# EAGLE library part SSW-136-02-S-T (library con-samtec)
THROUGH-HOLE .025" SQ POST SOCKET Source: Samtec SSW.pdf
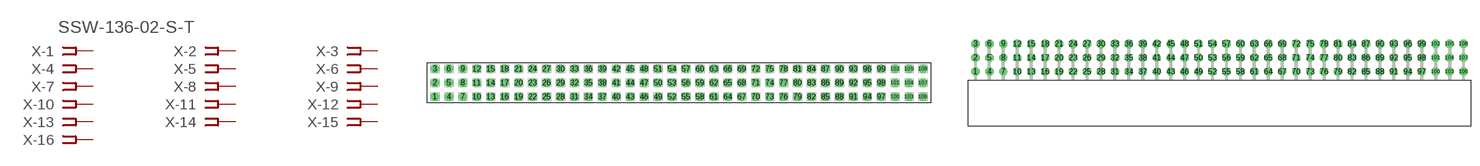
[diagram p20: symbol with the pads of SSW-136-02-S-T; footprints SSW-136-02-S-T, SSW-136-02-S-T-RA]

Designator prefix X; gates -1=FPINV -2=FPIN -3=FPIN -4=FPIN -5=FPIN -6=FPIN -7=FPIN -8=FPIN -9=FPIN -10=FPIN -11=FPIN -12=FPIN -13=FPIN -14=FPIN -15=FPIN -16=FPIN -17=FPIN -18=FPIN -19=FPIN -20=FPIN -21=FPIN -22=FPIN -23=FPIN -24=FPIN -25=FPIN -26=FPIN -27=FPIN -28=FPIN -29=FPIN -30=FPIN -31=FPIN -32=FPIN -33=FPIN -34=FPIN -35=FPIN -36=FPIN -37=FPIN -38=FPIN -39=FPIN -40=FPIN -41=FPIN -42=FPIN -43=FPIN -44=FPIN -45=FPIN -46=FPIN -47=FPIN -48=FPIN -49=FPIN -50=FPIN -51=FPIN -52=FPIN -53=FPIN -54=FPIN -55=FPIN -56=FPIN -57=FPIN -58=FPIN -59=FPIN -60=FPIN -61=FPIN -62=FPIN -63=FPIN -64=FPIN -65=FPIN -66=FPIN -67=FPIN -68=FPIN -69=FPIN -70=FPIN -71=FPIN -72=FPIN -73=FPIN -74=FPIN -75=FPIN -76=FPIN -77=FPIN -78=FPIN -79=FPIN -80=FPIN -81=FPIN -82=FPIN -83=FPIN -84=FPIN -85=FPIN -86=FPIN -87=FPIN -88=FPIN -89=FPIN -90=FPIN -91=FPIN -92=FPIN -93=FPIN -94=FPIN -95=FPIN -96=FPIN -97=FPIN -98=FPIN -99=FPIN -100=FPIN -101=FPIN -102=FPIN -103=FPIN -104=FPIN -105=FPIN -106=FPIN -107=FPIN -108=FPIN

## SSW-136-02-S-T (MPN: SSW-136-02-S-T; OC_FARNELL: unknown; OC_NEWARK: 83P0980)  [SSW-136-02-S-T]
1  -1:1  pas
2  -2:1  pas
3  -3:1  pas
4  -4:1  pas
5  -5:1  pas
6  -6:1  pas
7  -7:1  pas
8  -8:1  pas
9  -9:1  pas
10  -10:1  pas
11  -11:1  pas
12  -12:1  pas
13  -13:1  pas
14  -14:1  pas
15  -15:1  pas
16  -16:1  pas
17  -17:1  pas
18  -18:1  pas
19  -19:1  pas
20  -20:1  pas
21  -21:1  pas
22  -22:1  pas
23  -23:1  pas
24  -24:1  pas
25  -25:1  pas
26  -26:1  pas
27  -27:1  pas
28  -28:1  pas
29  -29:1  pas
30  -30:1  pas
31  -31:1  pas
32  -32:1  pas
33  -33:1  pas
34  -34:1  pas
35  -35:1  pas
36  -36:1  pas
37  -37:1  pas
38  -38:1  pas
39  -39:1  pas
40  -40:1  pas
41  -41:1  pas
42  -42:1  pas
43  -43:1  pas
44  -44:1  pas
45  -45:1  pas
46  -46:1  pas
47  -47:1  pas
48  -48:1  pas
49  -49:1  pas
50  -50:1  pas
51  -51:1  pas
52  -52:1  pas
53  -53:1  pas
54  -54:1  pas
55  -55:1  pas
56  -56:1  pas
57  -57:1  pas
58  -58:1  pas
59  -59:1  pas
60  -60:1  pas
61  -61:1  pas
62  -62:1  pas
63  -63:1  pas
64  -64:1  pas
65  -65:1  pas
66  -66:1  pas
67  -67:1  pas
68  -68:1  pas
69  -69:1  pas
70  -70:1  pas
71  -71:1  pas
72  -72:1  pas
73  -73:1  pas
74  -74:1  pas
75  -75:1  pas
76  -76:1  pas
77  -77:1  pas
78  -78:1  pas
79  -79:1  pas
80  -80:1  pas
81  -81:1  pas
82  -82:1  pas
83  -83:1  pas
84  -84:1  pas
85  -85:1  pas
86  -86:1  pas
87  -87:1  pas
88  -88:1  pas
89  -89:1  pas
90  -90:1  pas
91  -91:1  pas
92  -92:1  pas
93  -93:1  pas
94  -94:1  pas
95  -95:1  pas
96  -96:1  pas
97  -97:1  pas
98  -98:1  pas
99  -99:1  pas
100  -100:1  pas
101  -101:1  pas
102  -102:1  pas
103  -103:1  pas
104  -104:1  pas
105  -105:1  pas
106  -106:1  pas
107  -107:1  pas
108  -108:1  pas

## SSW-136-02-S-TRA (MPN: SSW-136-02-S-T-RA; OC_FARNELL: unknown; OC_NEWARK: 83P0981)  [SSW-136-02-S-T-RA]
Pads as for SSW-136-02-S-T

## Footprint SSW-136-02-S-T (pad centres in mm)
THROUGH-HOLE .025" SQ POST SOCKET Source: Samtec SSW.pdf
drill 1 pad 1.5 octagon: 1 -44.45,-2.54; 2 -44.45,0; 3 -44.45,2.54; 4 -41.91,-2.54; 5 -41.91,0; 6 -41.91,2.54; 7 -39.37,-2.54; 8 -39.37,0; 9 -39.37,2.54; 10 -36.83,-2.54; 11 -36.83,0; 12 -36.83,2.54; 13 -34.29,-2.54; 14 -34.29,0; 15 -34.29,2.54; 16 -31.75,-2.54; 17 -31.75,0; 18 -31.75,2.54; 19 -29.21,-2.54; 20 -29.21,0; 21 -29.21,2.54; 22 -26.67,-2.54; 23 -26.67,0; 24 -26.67,2.54; 25 -24.13,-2.54; 26 -24.13,0; 27 -24.13,2.54; 28 -21.59,-2.54; 29 -21.59,0; 30 -21.59,2.54; 31 -19.05,-2.54; 32 -19.05,0; 33 -19.05,2.54; 34 -16.51,-2.54; 35 -16.51,0; 36 -16.51,2.54; 37 -13.97,-2.54; 38 -13.97,0; 39 -13.97,2.54; 40 -11.43,-2.54; 41 -11.43,0; 42 -11.43,2.54; 43 -8.89,-2.54; 44 -8.89,0; 45 -8.89,2.54; 46 -6.35,-2.54; 47 -6.35,0; 48 -6.35,2.54; 49 -3.81,-2.54; 50 -3.81,0; 51 -3.81,2.54; 52 -1.27,-2.54; 53 -1.27,0; 54 -1.27,2.54; 55 1.27,-2.54; 56 1.27,0; 57 1.27,2.54; 58 3.81,-2.54; 59 3.81,0; 60 3.81,2.54; 61 6.35,-2.54; 62 6.35,0; 63 6.35,2.54; 64 8.89,-2.54; 65 8.89,0; 66 8.89,2.54; 67 11.43,-2.54; 68 11.43,0; 69 11.43,2.54; 70 13.97,-2.54; 71 13.97,0; 72 13.97,2.54; 73 16.51,-2.54; 74 16.51,0; 75 16.51,2.54; 76 19.05,-2.54; 77 19.05,0; 78 19.05,2.54; 79 21.59,-2.54; 80 21.59,0; 81 21.59,2.54; 82 24.13,-2.54; 83 24.13,0; 84 24.13,2.54; 85 26.67,-2.54; 86 26.67,0; 87 26.67,2.54; 88 29.21,-2.54; 89 29.21,0; 90 29.21,2.54; 91 31.75,-2.54; 92 31.75,0; 93 31.75,2.54; 94 34.29,-2.54; 95 34.29,0; 96 34.29,2.54; 97 36.83,-2.54; 98 36.83,0; 99 36.83,2.54; 100 39.37,-2.54; 101 39.37,0; 102 39.37,2.54; 103 41.91,-2.54; 104 41.91,0; 105 41.91,2.54; 106 44.45,-2.54; 107 44.45,0; 108 44.45,2.54

## Footprint SSW-136-02-S-T-RA (pad centres in mm)
THROUGH-HOLE .025" SQ POST SOCKET Source: Samtec SSW.pdf
drill 1 pad 1.5 octagon: 1 -44.45,1.524; 2 -44.45,4.064; 3 -44.45,6.604; 4 -41.91,1.524; 5 -41.91,4.064; 6 -41.91,6.604; 7 -39.37,1.524; 8 -39.37,4.064; 9 -39.37,6.604; 10 -36.83,1.524; 11 -36.83,4.064; 12 -36.83,6.604; 13 -34.29,1.524; 14 -34.29,4.064; 15 -34.29,6.604; 16 -31.75,1.524; 17 -31.75,4.064; 18 -31.75,6.604; 19 -29.21,1.524; 20 -29.21,4.064; 21 -29.21,6.604; 22 -26.67,1.524; 23 -26.67,4.064; 24 -26.67,6.604; 25 -24.13,1.524; 26 -24.13,4.064; 27 -24.13,6.604; 28 -21.59,1.524; 29 -21.59,4.064; 30 -21.59,6.604; 31 -19.05,1.524; 32 -19.05,4.064; 33 -19.05,6.604; 34 -16.51,1.524; 35 -16.51,4.064; 36 -16.51,6.604; 37 -13.97,1.524; 38 -13.97,4.064; 39 -13.97,6.604; 40 -11.43,1.524; 41 -11.43,4.064; 42 -11.43,6.604; 43 -8.89,1.524; 44 -8.89,4.064; 45 -8.89,6.604; 46 -6.35,1.524; 47 -6.35,4.064; 48 -6.35,6.604; 49 -3.81,1.524; 50 -3.81,4.064; 51 -3.81,6.604; 52 -1.27,1.524; 53 -1.27,4.064; 54 -1.27,6.604; 55 1.27,1.524; 56 1.27,4.064; 57 1.27,6.604; 58 3.81,1.524; 59 3.81,4.064; 60 3.81,6.604; 61 6.35,1.524; 62 6.35,4.064; 63 6.35,6.604; 64 8.89,1.524; 65 8.89,4.064; 66 8.89,6.604; 67 11.43,1.524; 68 11.43,4.064; 69 11.43,6.604; 70 13.97,1.524; 71 13.97,4.064; 72 13.97,6.604; 73 16.51,1.524; 74 16.51,4.064; 75 16.51,6.604; 76 19.05,1.524; 77 19.05,4.064; 78 19.05,6.604; 79 21.59,1.524; 80 21.59,4.064; 81 21.59,6.604; 82 24.13,1.524; 83 24.13,4.064; 84 24.13,6.604; 85 26.67,1.524; 86 26.67,4.064; 87 26.67,6.604; 88 29.21,1.524; 89 29.21,4.064; 90 29.21,6.604; 91 31.75,1.524; 92 31.75,4.064; 93 31.75,6.604; 94 34.29,1.524; 95 34.29,4.064; 96 34.29,6.604; 97 36.83,1.524; 98 36.83,4.064; 99 36.83,6.604; 100 39.37,1.524; 101 39.37,4.064; 102 39.37,6.604; 103 41.91,1.524; 104 41.91,4.064; 105 41.91,6.604; 106 44.45,1.524; 107 44.45,4.064; 108 44.45,6.604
